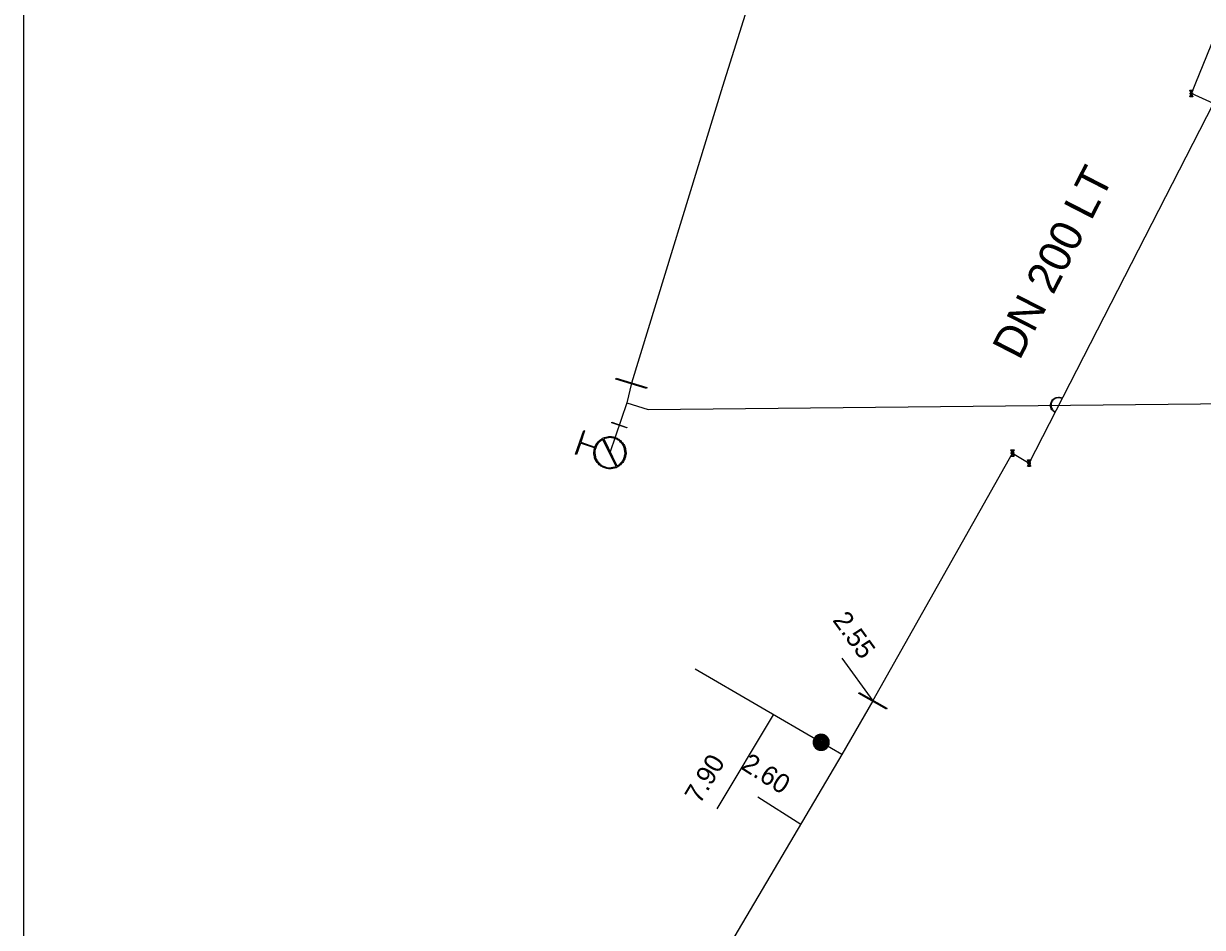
# Model space of a CAD drawing. Extents: x -820257 to -819974, y -1070894 to -1070484.
# Drawn here: x -820256.8 to -820183, y -1070745.2 to -1070688.6 of the extents above; entities that cross this region are included whole.
import ezdxf

# ---------------------------------------------------------------- set-up
doc = ezdxf.new("R2010")
doc.units = 0
for name, color, linetype in [('Default', 7, 'Continuous'), ('Hyd-odbočka', 7, 'Continuous'), ('Hyd-šoupě', 7, 'Continuous'), ('Hydrant', 7, 'Continuous'), ('Lomový bod vodovodu', 7, 'Continuous'), ('Nepropojené křížení vodovodu', 7, 'Continuous'), ('Oměrka vodovodu', 7, 'Continuous'), ('Oměrka-text', 7, 'Continuous'), ('Přípojka vodovodu', 7, 'Continuous'), ('Přípojkový uzávěr', 7, 'Continuous'), ('Roz-řad', 7, 'Continuous'), ('Roz-řad-popis základní', 7, 'Continuous'), ('Řad-šoupě', 7, 'Continuous')]:
    doc.layers.add(name, color=color, linetype=linetype)

msp = doc.modelspace()

# ---------------------------------------------------------------- linework, layer by layer
at = {"layer": 'Default'}
msp.add_lwpolyline([(-819975.603, -1070484.403), (-820256.81, -1070484.403), (-820256.81, -1070893.932)], dxfattribs=at)
at = {"layer": 'Hyd-odbočka'}
msp.add_line((-820219.039, -1070712.339), (-820220.11, -1070715.457), dxfattribs=at)
at = {"layer": 'Hyd-šoupě'}
msp.add_lwpolyline([(-820219.986, -1070713.555), (-820219.04, -1070713.88), (-820219.05, -1070713.91), (-820219.996, -1070713.585), (-820219.986, -1070713.555)], dxfattribs=at)
at = {"layer": 'Hydrant'}
for points in [[(-820221.066, -1070715.163), (-820221.953, -1070714.86), (-820222.196, -1070715.569), (-820222.255, -1070715.549), (-820221.749, -1070714.071), (-820221.69, -1070714.091), (-820221.933, -1070714.8), (-820221.046, -1070715.104)], [(-820219.723, -1070716.313), (-820220.55, -1070714.627)], [(-820220.496, -1070714.6), (-820219.667, -1070716.287)]]:
    msp.add_lwpolyline(points, dxfattribs=at)
for points in [[(-820221.046, -1070715.104), (-820220.962, -1070714.883), (-820220.774, -1070714.709), (-820220.575, -1070714.526), (-820220.304, -1070714.476), (-820220.034, -1070714.426), (-820219.786, -1070714.511), (-820219.54, -1070714.595), (-820219.357, -1070714.797), (-820219.175, -1070714.998), (-820219.127, -1070715.267), (-820219.079, -1070715.535), (-820219.163, -1070715.78), (-820219.247, -1070716.026), (-820219.449, -1070716.209), (-820219.651, -1070716.392), (-820219.919, -1070716.44), (-820220.187, -1070716.487), (-820220.433, -1070716.403), (-820220.681, -1070716.318), (-820220.864, -1070716.113), (-820221.048, -1070715.908), (-820221.093, -1070715.641), (-820221.136, -1070715.391), (-820221.066, -1070715.163)], [(-820220.55, -1070714.627), (-820220.649, -1070714.68), (-820220.733, -1070714.757), (-820220.92, -1070714.93), (-820220.997, -1070715.154), (-820221.073, -1070715.377), (-820221.031, -1070715.629), (-820220.989, -1070715.881), (-820220.817, -1070716.072), (-820220.646, -1070716.264), (-820220.413, -1070716.344), (-820220.182, -1070716.423), (-820219.931, -1070716.377), (-820219.821, -1070716.358), (-820219.723, -1070716.313)], [(-820219.667, -1070716.287), (-820219.573, -1070716.237), (-820219.492, -1070716.161), (-820219.301, -1070715.991), (-820219.222, -1070715.76), (-820219.143, -1070715.529), (-820219.188, -1070715.278), (-820219.233, -1070715.026), (-820219.404, -1070714.837), (-820219.575, -1070714.649), (-820219.806, -1070714.57), (-820220.039, -1070714.49), (-820220.293, -1070714.538), (-820220.401, -1070714.558), (-820220.496, -1070714.6)]]:
    msp.add_open_spline(points, degree=3, dxfattribs=at)
at = {"layer": 'Lomový bod vodovodu'}
for points in [[(-820183.748, -1070692.916), (-820183.81, -1070692.78), (-820183.61, -1070692.78), (-820183.673, -1070692.916)], [(-820183.688, -1070692.909), (-820183.634, -1070692.793), (-820183.788, -1070692.793), (-820183.733, -1070692.909)], [(-820183.673, -1070693.044), (-820183.61, -1070693.18), (-820183.81, -1070693.18), (-820183.748, -1070693.044)], [(-820183.733, -1070693.051), (-820183.788, -1070693.168), (-820183.634, -1070693.168), (-820183.688, -1070693.051)], [(-820183.742, -1070693.033), (-820183.718, -1070692.98), (-820183.742, -1070692.927)], [(-820183.728, -1070692.92), (-820183.71, -1070692.958), (-820183.693, -1070692.92)], [(-820183.693, -1070693.04), (-820183.71, -1070693.002), (-820183.728, -1070693.04)], [(-820183.678, -1070692.927), (-820183.702, -1070692.98), (-820183.678, -1070693.033)], [(-820194.948, -1070715.416), (-820195.01, -1070715.28), (-820194.81, -1070715.28), (-820194.873, -1070715.416)], [(-820194.873, -1070715.544), (-820194.81, -1070715.68), (-820195.01, -1070715.68), (-820194.948, -1070715.544)], [(-820194.888, -1070715.409), (-820194.834, -1070715.293), (-820194.988, -1070715.293), (-820194.933, -1070715.409)], [(-820194.933, -1070715.551), (-820194.988, -1070715.668), (-820194.834, -1070715.668), (-820194.888, -1070715.551)], [(-820194.942, -1070715.533), (-820194.918, -1070715.48), (-820194.942, -1070715.427)], [(-820194.928, -1070715.42), (-820194.91, -1070715.458), (-820194.893, -1070715.42)], [(-820194.893, -1070715.54), (-820194.91, -1070715.502), (-820194.928, -1070715.54)], [(-820194.878, -1070715.427), (-820194.902, -1070715.48), (-820194.878, -1070715.533)], [(-820193.908, -1070716.046), (-820193.97, -1070715.91), (-820193.77, -1070715.91), (-820193.833, -1070716.046)], [(-820193.833, -1070716.174), (-820193.77, -1070716.31), (-820193.97, -1070716.31), (-820193.908, -1070716.174)], [(-820193.848, -1070716.039), (-820193.794, -1070715.923), (-820193.948, -1070715.923), (-820193.893, -1070716.039)], [(-820193.893, -1070716.181), (-820193.948, -1070716.298), (-820193.794, -1070716.298), (-820193.848, -1070716.181)], [(-820193.902, -1070716.163), (-820193.878, -1070716.11), (-820193.902, -1070716.057)], [(-820193.888, -1070716.05), (-820193.87, -1070716.088), (-820193.853, -1070716.05)], [(-820193.853, -1070716.17), (-820193.87, -1070716.132), (-820193.888, -1070716.17)], [(-820193.838, -1070716.057), (-820193.862, -1070716.11), (-820193.838, -1070716.163)]]:
    msp.add_lwpolyline(points, dxfattribs=at)
for points in [[(-820183.748, -1070693.044), (-820183.765, -1070693.035), (-820183.775, -1070693.017), (-820183.785, -1070693), (-820183.785, -1070692.98), (-820183.785, -1070692.96), (-820183.775, -1070692.943), (-820183.765, -1070692.925), (-820183.748, -1070692.916)], [(-820183.742, -1070692.927), (-820183.756, -1070692.935), (-820183.764, -1070692.949), (-820183.772, -1070692.964), (-820183.772, -1070692.98), (-820183.772, -1070692.996), (-820183.764, -1070693.011), (-820183.756, -1070693.025), (-820183.742, -1070693.033)], [(-820183.733, -1070692.909), (-820183.722, -1070692.905), (-820183.71, -1070692.905), (-820183.699, -1070692.905), (-820183.688, -1070692.909)], [(-820183.688, -1070693.051), (-820183.698, -1070693.055), (-820183.71, -1070693.055), (-820183.722, -1070693.055), (-820183.733, -1070693.051)], [(-820183.693, -1070692.92), (-820183.701, -1070692.918), (-820183.71, -1070692.918), (-820183.719, -1070692.918), (-820183.728, -1070692.92)], [(-820183.728, -1070693.04), (-820183.719, -1070693.042), (-820183.71, -1070693.042), (-820183.701, -1070693.042), (-820183.693, -1070693.04)], [(-820183.678, -1070693.033), (-820183.664, -1070693.025), (-820183.656, -1070693.011), (-820183.648, -1070692.996), (-820183.648, -1070692.98), (-820183.648, -1070692.964), (-820183.656, -1070692.949), (-820183.664, -1070692.935), (-820183.678, -1070692.927)], [(-820183.673, -1070692.916), (-820183.655, -1070692.925), (-820183.645, -1070692.943), (-820183.635, -1070692.96), (-820183.635, -1070692.98), (-820183.635, -1070693), (-820183.645, -1070693.017), (-820183.655, -1070693.035), (-820183.673, -1070693.044)], [(-820194.948, -1070715.544), (-820194.965, -1070715.535), (-820194.975, -1070715.517), (-820194.985, -1070715.5), (-820194.985, -1070715.48), (-820194.985, -1070715.46), (-820194.975, -1070715.443), (-820194.965, -1070715.425), (-820194.948, -1070715.416)], [(-820194.942, -1070715.427), (-820194.956, -1070715.435), (-820194.964, -1070715.449), (-820194.972, -1070715.464), (-820194.972, -1070715.48), (-820194.972, -1070715.496), (-820194.964, -1070715.511), (-820194.956, -1070715.525), (-820194.942, -1070715.533)], [(-820194.933, -1070715.409), (-820194.922, -1070715.405), (-820194.91, -1070715.405), (-820194.899, -1070715.405), (-820194.888, -1070715.409)], [(-820194.888, -1070715.551), (-820194.898, -1070715.555), (-820194.91, -1070715.555), (-820194.922, -1070715.555), (-820194.933, -1070715.551)], [(-820194.893, -1070715.42), (-820194.901, -1070715.418), (-820194.91, -1070715.418), (-820194.919, -1070715.418), (-820194.928, -1070715.42)], [(-820194.928, -1070715.54), (-820194.919, -1070715.542), (-820194.91, -1070715.542), (-820194.901, -1070715.542), (-820194.893, -1070715.54)], [(-820194.878, -1070715.533), (-820194.864, -1070715.525), (-820194.856, -1070715.511), (-820194.848, -1070715.496), (-820194.848, -1070715.48), (-820194.848, -1070715.464), (-820194.856, -1070715.449), (-820194.864, -1070715.435), (-820194.878, -1070715.427)], [(-820194.873, -1070715.416), (-820194.855, -1070715.425), (-820194.845, -1070715.443), (-820194.835, -1070715.46), (-820194.835, -1070715.48), (-820194.835, -1070715.5), (-820194.845, -1070715.517), (-820194.855, -1070715.535), (-820194.873, -1070715.544)], [(-820193.908, -1070716.174), (-820193.925, -1070716.165), (-820193.935, -1070716.147), (-820193.945, -1070716.13), (-820193.945, -1070716.11), (-820193.945, -1070716.09), (-820193.935, -1070716.073), (-820193.925, -1070716.055), (-820193.908, -1070716.046)], [(-820193.902, -1070716.057), (-820193.916, -1070716.065), (-820193.924, -1070716.079), (-820193.932, -1070716.094), (-820193.932, -1070716.11), (-820193.932, -1070716.126), (-820193.924, -1070716.141), (-820193.916, -1070716.155), (-820193.902, -1070716.163)], [(-820193.893, -1070716.039), (-820193.882, -1070716.035), (-820193.87, -1070716.035), (-820193.859, -1070716.035), (-820193.848, -1070716.039)], [(-820193.848, -1070716.181), (-820193.858, -1070716.185), (-820193.87, -1070716.185), (-820193.882, -1070716.185), (-820193.893, -1070716.181)], [(-820193.853, -1070716.05), (-820193.861, -1070716.048), (-820193.87, -1070716.048), (-820193.879, -1070716.048), (-820193.888, -1070716.05)], [(-820193.888, -1070716.17), (-820193.879, -1070716.172), (-820193.87, -1070716.172), (-820193.861, -1070716.172), (-820193.853, -1070716.17)], [(-820193.838, -1070716.163), (-820193.824, -1070716.155), (-820193.816, -1070716.141), (-820193.808, -1070716.126), (-820193.808, -1070716.11), (-820193.808, -1070716.094), (-820193.816, -1070716.079), (-820193.824, -1070716.065), (-820193.838, -1070716.057)], [(-820193.833, -1070716.046), (-820193.815, -1070716.055), (-820193.805, -1070716.073), (-820193.795, -1070716.09), (-820193.795, -1070716.11), (-820193.795, -1070716.13), (-820193.805, -1070716.147), (-820193.815, -1070716.165), (-820193.833, -1070716.174)]]:
    msp.add_open_spline(points, degree=3, dxfattribs=at)
at = {"layer": 'Nepropojené křížení vodovodu'}
for points in [[(-820191.795, -1070712.043), (-820191.809, -1070712.071)], [(-820192.237, -1070712.905), (-820192.251, -1070712.933)]]:
    msp.add_lwpolyline(points, dxfattribs=at)
for points in [[(-820192.251, -1070712.933), (-820192.367, -1070712.873), (-820192.444, -1070712.759), (-820192.52, -1070712.644), (-820192.523, -1070712.508), (-820192.526, -1070712.373), (-820192.468, -1070712.26), (-820192.41, -1070712.148), (-820192.298, -1070712.071), (-820192.186, -1070711.994), (-820192.049, -1070711.989), (-820191.911, -1070711.984), (-820191.795, -1070712.043)], [(-820191.809, -1070712.071), (-820191.918, -1070712.015), (-820192.047, -1070712.02), (-820192.176, -1070712.026), (-820192.281, -1070712.097), (-820192.386, -1070712.169), (-820192.44, -1070712.275), (-820192.494, -1070712.38), (-820192.491, -1070712.507), (-820192.489, -1070712.635), (-820192.417, -1070712.742), (-820192.346, -1070712.849), (-820192.237, -1070712.905)]]:
    msp.add_open_spline(points, degree=3, dxfattribs=at)
at = {"layer": 'Oměrka vodovodu'}
for p, q in [((-820205.587, -1070728.309), (-820203.65, -1070730.98)), ((-820213.403, -1070737.738), (-820209.866, -1070731.853)), ((-820210.859, -1070736.987), (-820208.16, -1070738.701))]:
    msp.add_line(p, q, dxfattribs=at)
at = {"layer": 'Přípojka vodovodu'}
msp.add_lwpolyline([(-820205.582, -1070734.336), (-820206.88, -1070733.584), (-820214.779, -1070729.005)], dxfattribs=at)
at = {"layer": 'Přípojkový uzávěr'}
for points in [[(-820206.629, -1070733.15), (-820206.52, -1070733.214), (-820206.449, -1070733.329), (-820206.378, -1070733.445), (-820206.38, -1070733.583), (-820206.382, -1070733.721), (-820206.447, -1070733.834), (-820206.512, -1070733.947), (-820206.629, -1070734.017), (-820206.746, -1070734.086), (-820206.882, -1070734.084), (-820207.018, -1070734.081), (-820207.131, -1070734.016), (-820207.243, -1070733.951), (-820207.313, -1070733.834), (-820207.383, -1070733.717), (-820207.38, -1070733.581), (-820207.378, -1070733.445), (-820207.313, -1070733.333), (-820207.247, -1070733.22), (-820207.128, -1070733.149), (-820207.01, -1070733.079), (-820206.874, -1070733.083), (-820206.739, -1070733.087), (-820206.629, -1070733.15)], [(-820206.653, -1070733.191), (-820206.752, -1070733.134), (-820206.875, -1070733.13), (-820206.998, -1070733.126), (-820207.105, -1070733.19), (-820207.212, -1070733.254), (-820207.272, -1070733.356), (-820207.331, -1070733.458), (-820207.333, -1070733.581), (-820207.336, -1070733.704), (-820207.272, -1070733.81), (-820207.209, -1070733.916), (-820207.107, -1070733.975), (-820207.005, -1070734.034), (-820206.882, -1070734.037), (-820206.758, -1070734.039), (-820206.652, -1070733.976), (-820206.547, -1070733.913), (-820206.488, -1070733.811), (-820206.428, -1070733.708), (-820206.427, -1070733.583), (-820206.425, -1070733.458), (-820206.49, -1070733.353), (-820206.554, -1070733.248), (-820206.653, -1070733.191)], [(-820206.67, -1070733.22), (-820206.578, -1070733.274), (-820206.519, -1070733.37), (-820206.46, -1070733.467), (-820206.461, -1070733.583), (-820206.462, -1070733.699), (-820206.517, -1070733.794), (-820206.572, -1070733.888), (-820206.67, -1070733.947), (-820206.767, -1070734.005), (-820206.881, -1070734.003), (-820206.996, -1070734), (-820207.09, -1070733.945), (-820207.184, -1070733.891), (-820207.243, -1070733.793), (-820207.302, -1070733.695), (-820207.299, -1070733.581), (-820207.297, -1070733.468), (-820207.242, -1070733.373), (-820207.187, -1070733.278), (-820207.088, -1070733.219), (-820206.989, -1070733.16), (-820206.875, -1070733.164), (-820206.761, -1070733.168), (-820206.67, -1070733.22)], [(-820206.692, -1070733.258), (-820206.828, -1070733.18), (-820206.977, -1070733.22), (-820207.126, -1070733.261), (-820207.204, -1070733.396), (-820207.282, -1070733.53), (-820207.242, -1070733.68), (-820207.202, -1070733.83), (-820207.069, -1070733.907), (-820206.933, -1070733.985), (-820206.783, -1070733.946), (-820206.633, -1070733.906), (-820206.555, -1070733.772), (-820206.477, -1070733.637), (-820206.517, -1070733.487), (-820206.556, -1070733.337), (-820206.692, -1070733.258)], [(-820206.715, -1070733.298), (-820206.597, -1070733.367), (-820206.562, -1070733.498), (-820206.528, -1070733.629), (-820206.596, -1070733.746), (-820206.664, -1070733.864), (-820206.796, -1070733.899), (-820206.927, -1070733.934), (-820207.045, -1070733.866), (-820207.163, -1070733.797), (-820207.198, -1070733.666), (-820207.232, -1070733.535), (-820207.164, -1070733.417), (-820207.096, -1070733.299), (-820206.965, -1070733.264), (-820206.834, -1070733.229), (-820206.715, -1070733.298)], [(-820206.735, -1070733.332), (-820206.839, -1070733.272), (-820206.954, -1070733.303), (-820207.07, -1070733.334), (-820207.13, -1070733.437), (-820207.19, -1070733.541), (-820207.159, -1070733.656), (-820207.129, -1070733.771), (-820207.025, -1070733.831), (-820206.921, -1070733.891), (-820206.806, -1070733.861), (-820206.69, -1070733.83), (-820206.63, -1070733.727), (-820206.57, -1070733.623), (-820206.601, -1070733.508), (-820206.631, -1070733.393), (-820206.735, -1070733.332)], [(-820206.755, -1070733.367), (-820206.664, -1070733.419), (-820206.638, -1070733.519), (-820206.611, -1070733.619), (-820206.664, -1070733.709), (-820206.716, -1070733.799), (-820206.816, -1070733.825), (-820206.915, -1070733.851), (-820207.005, -1070733.799), (-820207.095, -1070733.748), (-820207.121, -1070733.648), (-820207.148, -1070733.548), (-820207.096, -1070733.458), (-820207.044, -1070733.368), (-820206.945, -1070733.341), (-820206.845, -1070733.314), (-820206.755, -1070733.367)], [(-820206.778, -1070733.407), (-820206.851, -1070733.364), (-820206.932, -1070733.386), (-820207.013, -1070733.408), (-820207.056, -1070733.481), (-820207.098, -1070733.554), (-820207.076, -1070733.635), (-820207.055, -1070733.716), (-820206.982, -1070733.758), (-820206.909, -1070733.8), (-820206.828, -1070733.779), (-820206.746, -1070733.757), (-820206.704, -1070733.684), (-820206.662, -1070733.611), (-820206.683, -1070733.53), (-820206.705, -1070733.449), (-820206.778, -1070733.407)], [(-820206.795, -1070733.437), (-820206.735, -1070733.472), (-820206.717, -1070733.539), (-820206.699, -1070733.606), (-820206.734, -1070733.667), (-820206.769, -1070733.728), (-820206.837, -1070733.746), (-820206.904, -1070733.763), (-820206.964, -1070733.728), (-820207.025, -1070733.693), (-820207.043, -1070733.626), (-820207.061, -1070733.559), (-820207.026, -1070733.498), (-820206.99, -1070733.437), (-820206.923, -1070733.419), (-820206.856, -1070733.401), (-820206.795, -1070733.437)], [(-820206.817, -1070733.475), (-820206.862, -1070733.449), (-820206.912, -1070733.462), (-820206.962, -1070733.476), (-820206.988, -1070733.52), (-820207.014, -1070733.565), (-820207, -1070733.615), (-820206.987, -1070733.665), (-820206.943, -1070733.691), (-820206.898, -1070733.717), (-820206.848, -1070733.704), (-820206.797, -1070733.691), (-820206.772, -1070733.646), (-820206.746, -1070733.601), (-820206.759, -1070733.551), (-820206.772, -1070733.501), (-820206.817, -1070733.475)], [(-820206.841, -1070733.515), (-820206.812, -1070733.532), (-820206.804, -1070733.563), (-820206.796, -1070733.593), (-820206.813, -1070733.622), (-820206.829, -1070733.65), (-820206.86, -1070733.659), (-820206.891, -1070733.667), (-820206.919, -1070733.651), (-820206.947, -1070733.634), (-820206.956, -1070733.603), (-820206.964, -1070733.572), (-820206.948, -1070733.544), (-820206.931, -1070733.515), (-820206.9, -1070733.507), (-820206.869, -1070733.499), (-820206.841, -1070733.515)], [(-820206.857, -1070733.542), (-820206.873, -1070733.533), (-820206.892, -1070733.537), (-820206.911, -1070733.542), (-820206.921, -1070733.559), (-820206.93, -1070733.576), (-820206.925, -1070733.595), (-820206.921, -1070733.614), (-820206.904, -1070733.623), (-820206.886, -1070733.634), (-820206.868, -1070733.628), (-820206.849, -1070733.623), (-820206.84, -1070733.606), (-820206.83, -1070733.589), (-820206.834, -1070733.571), (-820206.839, -1070733.552), (-820206.857, -1070733.542)]]:
    msp.add_open_spline(points, degree=3, dxfattribs=at)
at = {"layer": 'Roz-řad'}
msp.add_line((-820218.767, -1070711.114), (-820219.039, -1070712.339), dxfattribs=at)
for points in [[(-820190.84, -1070620.738), (-820198.53, -1070645.709), (-820201.034, -1070653.842), (-820205.362, -1070667.895), (-820207.714, -1070675.535), (-820211.419, -1070687.296), (-820213.068, -1070692.533), (-820218.767, -1070711.114)], [(-820203.65, -1070730.98), (-820194.91, -1070715.48), (-820193.87, -1070716.11), (-820182.33, -1070693.6), (-820183.71, -1070692.98), (-820178.78, -1070680.85), (-820175.51, -1070672.3), (-820175.3, -1070660.58), (-820174.05, -1070658.3)], [(-820219.039, -1070712.339), (-820217.709, -1070712.762), (-820146.528, -1070712.014)], [(-820203.65, -1070730.98), (-820205.582, -1070734.336), (-820221.572, -1070761.413), (-820233.361, -1070780.756), (-820248.521, -1070812.849), (-820248.13, -1070847.392), (-820246.14, -1070854.184)]]:
    msp.add_lwpolyline(points, dxfattribs=at)
at = {"layer": 'Řad-šoupě'}
for points in [[(-820219.713, -1070710.79), (-820217.8, -1070711.377), (-820217.819, -1070711.437), (-820219.731, -1070710.85), (-820219.713, -1070710.79)], [(-820202.794, -1070731.499), (-820204.537, -1070730.517), (-820204.506, -1070730.462), (-820202.764, -1070731.444), (-820202.794, -1070731.499)]]:
    msp.add_lwpolyline(points, dxfattribs=at)

# ---------------------------------------------------------------- texts
at = {"layer": 'Oměrka-text'}
for s, rotation, p in [(' 2.55', 305.94949, (-820206.472, -1070725.582)), (' 7.90', 58.99334, (-820214.703, -1070737.872)), (' 2.60', 327.58237, (-820212.343, -1070734.966))]:
    msp.add_text(s, height=1.2, rotation=rotation, dxfattribs=at).set_placement(p)
at = {"layer": 'Roz-řad-popis základní'}
msp.add_text('DN 200 LT', height=2, rotation=62.85754, dxfattribs=at).set_placement((-820194.468, -1070709.729))

doc.saveas('drawing.dxf')
